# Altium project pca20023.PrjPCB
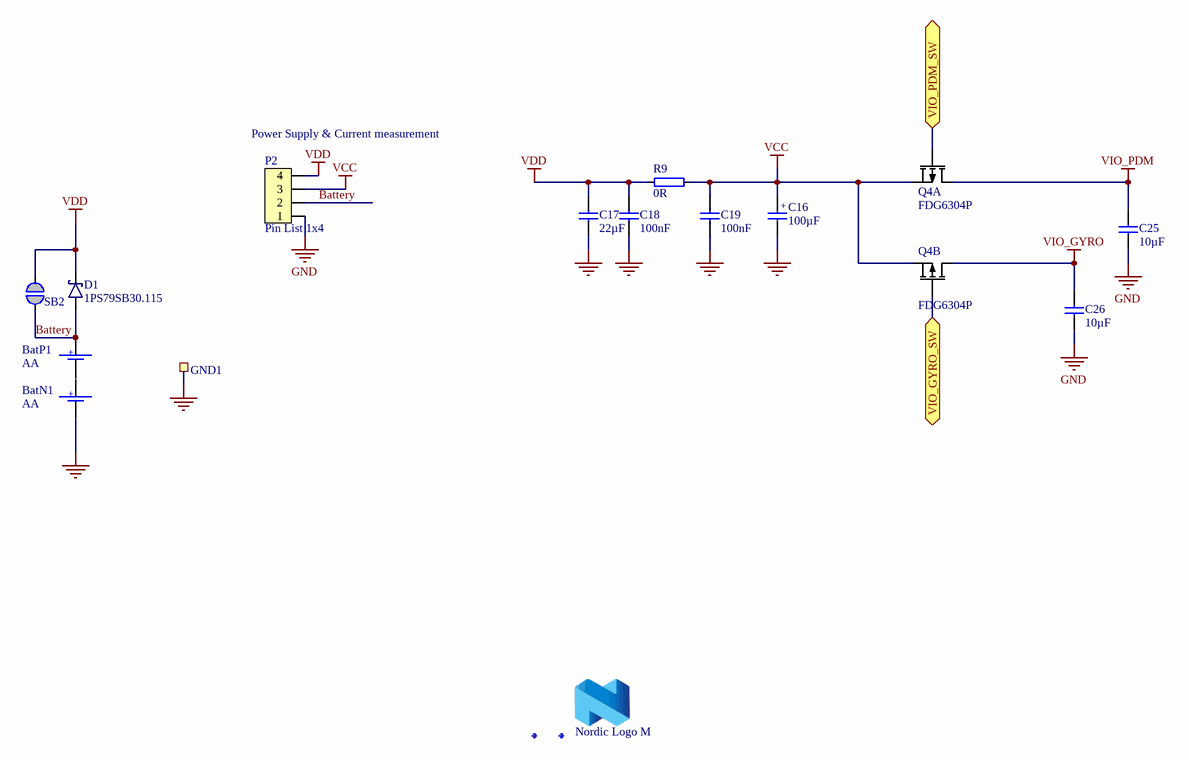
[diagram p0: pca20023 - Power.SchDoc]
5 sheets, 173 parts. Net scope: flat (ports and power ports of the same name join across sheets).
Board file: 400198.PcbDoc
Sheets:
  pca20023 - Power.SchDoc
  pca20023 - Keyboard.SchDoc
  pca20023 - Sensors.SchDoc
  pca20023 - IR&Mic&Buzzer.SchDoc
  pca20023 - Radio.SchDoc

## Sheet pca20023 - Power.SchDoc: Smart Remote 3 nRF52 Product Example - Power
size A4; DocumentNumber: 3; Revision: 1.0.0; SheetNumber: 2; SheetTotal: 5; DrawnBy: TORS; ProjectNumber: 4414; DocumentSize: A4; PCBRevision: 0044TORS; PCAName: PCA20023; PCBNumber: 400198

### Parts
BatN1  AA  [POLSATBATTERYHOLDER]
BatP1  AA  [POLSATBATTERYHOLDER]
C16  100µF  [CAPMP3528X21N]
C17  22µF  [CAPC2012X11L]
C18  100nF  [CAPC1005X04L]
C19  100nF  [CAPC1005X04L]
C25  10µF  [CAPC1608X06L]
C26  10µF  [CAPC1608X06L]
D1  1PS79SB30.115  [SOD-523]
Fid1  Fiducial mark  [Fiducial]  (value not drawn)
Fid2  Fiducial mark  [Fiducial]  (value not drawn)
GND1  2.0mm,SMD  [TP_SMD_2.0mmX2.0mm]  (value not drawn)  (no BOM)
LOGO1  Nordic Logo M  [NORDIC_LOGO_M]  (no BOM)
P2  Pin List 1x4  [LIST_1x4_SMD]
Q4  FDG6304P  [SOT65P210X100-6N]  (parts A,B of 2)
R9  0R  [RESC1005X04L]
SB2  Solderbridge  [Solderbridge]  (value not drawn)  (no BOM)

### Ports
VIO_GYRO_SW (bidir), VIO_PDM_SW (bidir)

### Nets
GND: BatN1.1 C16.2 C17.1 C18.1 C19.1 C25.1 C26.1 GND1.1 P2.1
VCC: C16.1 C19.2 P2.3 Q4.1(S1) Q4.4(S2) R9.2
VDD: C17.2 C18.2 D1.3(C) P2.4 R9.1 SB2.1
VIO_GYRO: C26.2 Q4.3(D2)
VIO_PDM: C25.2 Q4.6(D1)
Battery: BatP1.1 D1.1(A) P2.2 SB2.2
P0.07: Q4.5(G2) ; port VIO_GYRO_SW
P0.26: Q4.2(G1) ; port VIO_PDM_SW

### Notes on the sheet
- (near P2) Power Supply & Current measurement

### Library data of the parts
BatN1 = POLSATBATTERYHOLDER_N: Polsat Battery holder, Negative pole; Manufacturer Part Number: NA; Artikkelnr Noca: N.A.
BatP1 = POLSATBATTERYHOLDER_P: Polsat Battery holder, Positive pole; Manufacturer Part Number: NA; Artikkelnr Noca: N.A.
C16 = C3528-100µF: Capacitor, Tantalum, ±10%; Manufacturer: Vishay Sprague; Manufacturer Part Number: TR3B107K6R3C0500; Note: 6.3V; Artikkelnr Noca: N.A.
C17 = C0805-22µ: Capacitor, X5R, ±10%; Note: 6.3V; Artikkelnr Noca: 20039330; Artikkelnr Simpro: N.A.
C18 C19 = C0402-100n: Capacitor, X7R, ±10%; Note: 16V; Artikkelnr Noca: 20039200; Artikkelnr Simpro: N.A.
C25 C26 = C0603-10µ: Capacitor, X5R, ±20%; Note: 6.3V; Artikkelnr Noca: 20039234; Artikkelnr Simpro: N.A.
D1 = 1PS79SB30.115: Diode Schottky Vf=0.38, Vr=40V, If=200mA, Ir=500nA; Manufacturer: NXP; 2nd source part number: 873-4097; Artikkelnr Noca: 10029120; Artikkelnr Simpro: N.A.
Fid1 Fid2 = Fid-Mark: Artikkelnr Noca: N.A.
GND1 = TP_SMD_2.0MM: 2.0x2.0mm SMD testpad; Manufacturer: Nordic Semiconductor; Artikkelnr Noca: N.A.
LOGO1 = Nordic Logo M: Nordic Logo, medium size; Artikkelnr Noca: N.A.
P2 = Pin List 1x4 SMD: Pin List 1x4, 2.54mm (100mil), SMD; 2nd source part number: 179-8983; Artikkelnr Noca: 55019234; Artikkelnr Simpro: N.A.
Q4 = FDG6304P: Fairchild, FDG6304P, Dual P-Channel Digital FET; Manufacturer Part Number: FDG6304N; 2nd source part number: FDG6304PCT-ND; Artikkelnr Noca: 35029088; Artikkelnr Simpro: N.A.
R9 = R0402-0R: Resistor, ±5%, 0.063W; Note: Chip Res 5%; Artikkelnr Noca: 27049000; Artikkelnr Simpro: N.A.; Value Ohm: 0
SB2 = Solderbridge: Artikkelnr Noca: N.A.

## Sheet pca20023 - Keyboard.SchDoc: Smart Remote 3 nRF52 Product Example - Keyboard
size A4; DocumentNumber: 4; Revision: 1.0.0; SheetNumber: 3; SheetTotal: 5; DrawnBy: TORS; ProjectNumber: 4414; DocumentSize: A4; PCBRevision: 0044TORS; PCAName: PCA20023; PCBNumber: 400198
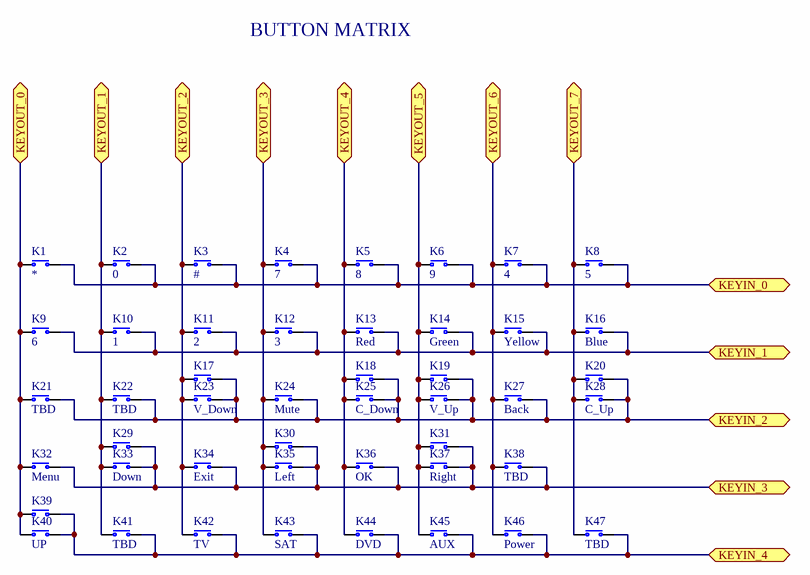
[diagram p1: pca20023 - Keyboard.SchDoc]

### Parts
K1  *  [PCB Switch]  (no BOM)
K2  0  [PCB Switch]  (no BOM)
K3  #  [PCB Switch]  (no BOM)
K4  7  [PCB Switch]  (no BOM)
K5  8  [PCB Switch]  (no BOM)
K6  9  [PCB Switch]  (no BOM)
K7  4  [PCB Switch]  (no BOM)
K8  5  [PCB Switch]  (no BOM)
K9  6  [PCB Switch]  (no BOM)
K10  1  [PCB Switch]  (no BOM)
K11  2  [PCB Switch]  (no BOM)
K12  3  [PCB Switch]  (no BOM)
K13  Red  [PCB Switch]  (no BOM)
K14  Green  [PCB Switch]  (no BOM)
K15  Yellow  [PCB Switch]  (no BOM)
K16  Blue  [PCB Switch]  (no BOM)
K17  PCB SW  [PCB Switch]  (value not drawn)  (no BOM)
K18  PCB SW  [PCB Switch]  (value not drawn)  (no BOM)
K19  PCB SW  [PCB Switch]  (value not drawn)  (no BOM)
K20  PCB SW  [PCB Switch]  (value not drawn)  (no BOM)
K21  TBD  [PCB Switch]  (no BOM)
K22  TBD  [PCB Switch]  (no BOM)
K23  V_Down  [PCB Switch]  (no BOM)
K24  Mute  [PCB Switch]  (no BOM)
K25  C_Down  [PCB Switch]  (no BOM)
K26  V_Up  [PCB Switch]  (no BOM)
K27  Back  [PCB Switch]  (no BOM)
K28  C_Up  [PCB Switch]  (no BOM)
K29  PCB SW  [PCB Switch]  (value not drawn)  (no BOM)
K30  PCB SW  [PCB Switch]  (value not drawn)  (no BOM)
K31  PCB SW  [PCB Switch]  (value not drawn)  (no BOM)
K32  Menu  [PCB Switch]  (no BOM)
K33  Down  [PCB Switch]  (no BOM)
K34  Exit  [PCB Switch]  (no BOM)
K35  Left  [PCB Switch]  (no BOM)
K36  OK  [PCB Switch]  (no BOM)
K37  Right  [PCB Switch]  (no BOM)
K38  TBD  [PCB Switch]  (no BOM)
K39  PCB SW  [PCB Switch]  (value not drawn)  (no BOM)
K40  UP  [PCB Switch]  (no BOM)
K41  TBD  [PCB Switch]  (no BOM)
K42  TV  [PCB Switch]  (no BOM)
K43  SAT  [PCB Switch]  (no BOM)
K44  DVD  [PCB Switch]  (no BOM)
K45  AUX  [PCB Switch]  (no BOM)
K46  Power  [PCB Switch]  (no BOM)
K47  TBD  [PCB Switch]  (no BOM)

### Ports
KEYIN_0 (bidir), KEYIN_1 (bidir), KEYIN_2 (bidir), KEYIN_3 (bidir), KEYIN_4 (bidir), KEYOUT_0 (bidir), KEYOUT_1 (bidir), KEYOUT_2 (bidir), KEYOUT_3 (bidir), KEYOUT_4 (bidir), KEYOUT_5 (bidir), KEYOUT_6 (bidir), KEYOUT_7 (bidir)

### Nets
P0.03: K5.2(COM) K13.2(COM) K18.2(COM) K25.2(COM) K36.2(COM) K44.2(COM) ; port KEYOUT_4
P0.08: K3.2(COM) K11.2(COM) K17.2(COM) K23.2(COM) K34.2(COM) K42.2(COM) ; port KEYOUT_2
P0.11: K4.2(COM) K12.2(COM) K24.2(COM) K30.2(COM) K35.2(COM) K43.2(COM) ; port KEYOUT_3
P0.12: K1.2(COM) K9.2(COM) K21.2(COM) K32.2(COM) K39.2(COM) K40.2(COM) ; port KEYOUT_0
P0.16: K1.1(N.O) K2.1(N.O) K3.1(N.O) K4.1(N.O) K5.1(N.O) K6.1(N.O) K7.1(N.O) K8.1(N.O) ; port KEYIN_0
P0.17: K9.1(N.O) K10.1(N.O) K11.1(N.O) K12.1(N.O) K13.1(N.O) K14.1(N.O) K15.1(N.O) K16.1(N.O) ; port KEYIN_1
P0.18: K17.1(N.O) K18.1(N.O) K19.1(N.O) K20.1(N.O) K21.1(N.O) K22.1(N.O) K23.1(N.O) K24.1(N.O) K25.1(N.O) K26.1(N.O) K27.1(N.O) K28.1(N.O) ; port KEYIN_2
P0.19: K39.1(N.O) K40.1(N.O) K41.1(N.O) K42.1(N.O) K43.1(N.O) K44.1(N.O) K45.1(N.O) K46.1(N.O) K47.1(N.O) ; port KEYIN_4
P0.20: K7.2(COM) K15.2(COM) K27.2(COM) K38.2(COM) K46.2(COM) ; port KEYOUT_6
P0.25: K8.2(COM) K16.2(COM) K20.2(COM) K28.2(COM) K47.2(COM) ; port KEYOUT_7
P0.27: K6.2(COM) K14.2(COM) K19.2(COM) K26.2(COM) K31.2(COM) K37.2(COM) K45.2(COM) ; port KEYOUT_5
P0.28: K2.2(COM) K10.2(COM) K22.2(COM) K29.2(COM) K33.2(COM) K41.2(COM) ; port KEYOUT_1
P0.29: K29.1(N.O) K30.1(N.O) K31.1(N.O) K32.1(N.O) K33.1(N.O) K34.1(N.O) K35.1(N.O) K36.1(N.O) K37.1(N.O) K38.1(N.O) ; port KEYIN_3

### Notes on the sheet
- BUTTON MATRIX

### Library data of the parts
K1-K16 K21-K28 K32-K38 K40-K47 = KEY_SWITCH_SR3: Keyboard matrix switch; Value: PCB SW; Artikkelnr Noca: N.A.
K17-K20 K29-K31 K39 = KEY_SWITCH_SR3: Keyboard matrix switch; Artikkelnr Noca: N.A.

## Sheet pca20023 - Sensors.SchDoc: Smart Remote 3 nRF52 Product Example - Sensors
size A4; DocumentNumber: 5; Revision: 1.0.0; SheetNumber: 4; SheetTotal: 5; DrawnBy: TORS; ProjectNumber: 4414; DocumentSize: A4; PCBRevision: 0044TORS; PCAName: PCA20023; PCBNumber: 400198
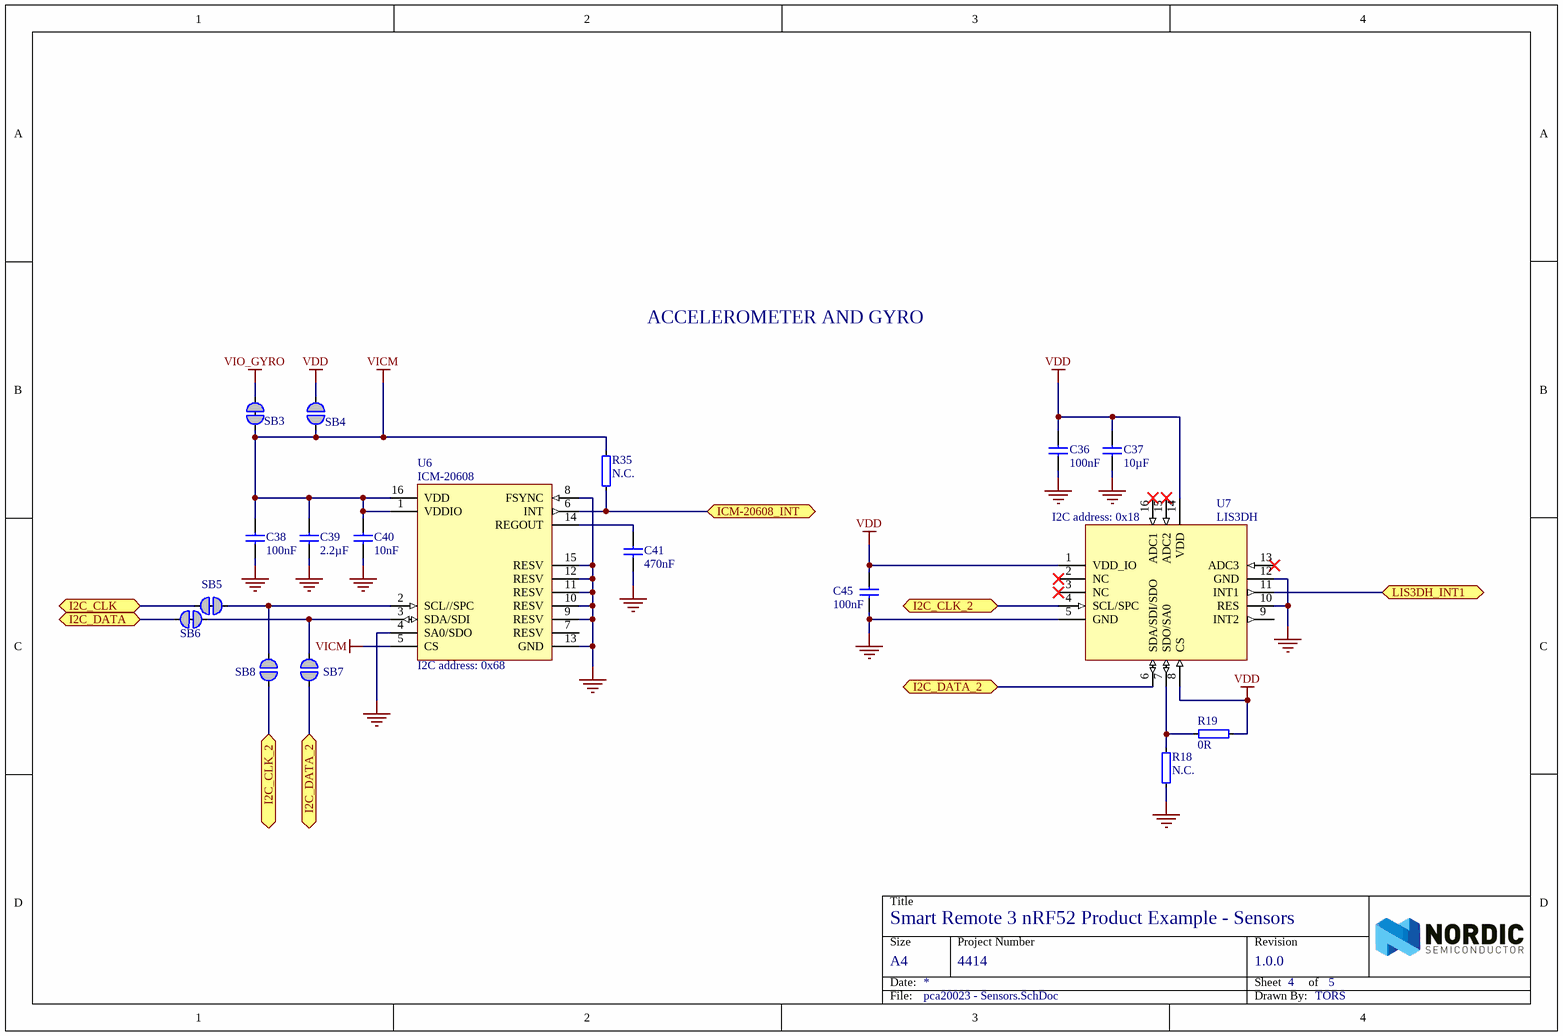
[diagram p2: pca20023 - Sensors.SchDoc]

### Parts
C36  100nF  [CAPC1005X04L]
C37  10µF  [CAPC2012X11L]
C38  100nF  [CAPC1005X04L]
C39  2.2µF  [CAPC1005X04L]
C40  10nF  [CAPC1005X04L]
C41  470nF  [CAPC1005X04L]
C45  100nF  [CAPC1005X04L]
R18  N.C.  [RESC1005X04L]
R19  0R  [RESC1005X04L]
R35  N.C.  [RESC1005X04L]
SB3  Solderbridge  [Solderbridge_Shorted]  (value not drawn)  (net tie, no BOM)
SB4  Solderbridge  [Solderbridge]  (value not drawn)  (no BOM)
SB5  Solderbridge  [Solderbridge_Shorted]  (value not drawn)  (net tie, no BOM)
SB6  Solderbridge  [Solderbridge_Shorted]  (value not drawn)  (net tie, no BOM)
SB7  Solderbridge  [Solderbridge]  (value not drawn)  (no BOM)
SB8  Solderbridge  [Solderbridge]  (value not drawn)  (no BOM)
U6  ICM-20608  [PQFN50P300X300X100-16N]
U7  LIS3DH  [PQFN50P300X300X100-16N]

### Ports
I2C_CLK (bidir), I2C_CLK_2 (bidir), I2C_DATA (bidir), I2C_DATA_2 (bidir), ICM-20608_INT (bidir), LIS3DH_INT1 (bidir)

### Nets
GND: C36.1 C37.1 C38.1 C39.1 C40.1 C41.1 C45.1 R18.1 U6.4(SA0/SDO) U6.8(FSYNC) U6.9(RESV) U6.10(RESV) U6.11(RESV) U6.12(RESV) U6.13(GND) U6.15(RESV) U7.5(GND) U7.10(RES) U7.12(GND)
VDD: C36.2 C37.2 C45.2 R19.2 SB4.1 U7.1(VDD_IO) U7.8(CS) U7.14(VDD)
VICM: C38.2 C39.2 C40.2 R35.2 SB3.2 SB4.2 U6.1(VDDIO) U6.5(CS) U6.16(VDD)
VIO_GYRO: SB3.1
P0.13: SB7.2 U7.6(SDA/SDI/SDO) ; port I2C_DATA_2
P0.14: SB8.2 U7.4(SCL/SPC) ; port I2C_CLK_2
P0.15: SB5.1 ; port I2C_CLK
P0.22: R35.1 U6.6(INT) ; port ICM-20608_INT
P0.30: U7.11(INT1) ; port LIS3DH_INT1
P0.31: SB6.1 ; port I2C_DATA
NetC41_2: C41.2 U6.14(REGOUT)
NetR18_2: R18.2 R19.1 U7.7(SDO/SA0)
NetSB5_2: SB5.2 SB8.1 U6.2(SCL//SPC)
NetSB6_2: SB6.2 SB7.1 U6.3(SDA/SDI)

Not connected (* = marked no-connect by the designer): U6 7(RESV); U7 2(NC)* 3(NC)* 9(INT2) 13(ADC3)* 15(ADC2)* 16(ADC1)*

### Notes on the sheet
- ACCELEROMETER AND GYRO
- (near U7) I2C address: 0x18
- (near U6) I2C address: 0x68

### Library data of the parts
C36 C38 C45 = C0402-100n: as C18 on sheet pca20023 - Power
C37 = C0805-10µ: Capacitor, X5R, ±10%; Note: 16V; Artikkelnr Noca: 20039243; Artikkelnr Simpro: N.A.
C39 = C0402-2µ2: Capacitor, X5R, ±20%; Note: 25V; Artikkelnr Noca: 20030006; Artikkelnr Simpro: N.A.
C40 = C0402-10n: Capacitor, X7R, ±10%; Note: 16V; Artikkelnr Noca: 20039166; Artikkelnr Simpro: N.A.
C41 = C0402-470n: Capacitor, X5R, ±10%; Note: 6.3V; Artikkelnr Noca: 20039350; Artikkelnr Simpro: N.A.
R18 R35 = R0402-N.C.: Not mounted; Note: Chip Res; Artikkelnr Noca: N.A.; Assembly: Not mounted
R19 = R0402-0R: as R9 on sheet pca20023 - Power
SB3 SB5 SB6 = Solderbridge Shorted: Shorted Solderbridge; Artikkelnr Noca: N.A.
SB4 SB7 SB8 = Solderbridge: Artikkelnr Noca: N.A.
U6 = ICM-20608: Gyroscope and Accelerometer, PQFN-16; Manufacturer: InvenSense; Artikkelnr Noca: N.A.
U7 = LIS3DH: 3-axis - ±2g/±4g/±8g/±16g digital output nano accelerometer; Manufacturer: STMicroelectronics; 2nd source part number: 187-2923; Note: MEMS digital output motion sensor ultra low-power high performance 3-axes "nano" accelerometer; Artikkelnr Noca: 15079978; Artikkelnr Simpro: N.A.

## Sheet pca20023 - IR&Mic&Buzzer.SchDoc: Smart Remote 3 nRF52 Product Example - IR&Mic&Buzzer
size A4; DocumentNumber: 5; Revision: 1.0.0; SheetNumber: 5; SheetTotal: 5; DrawnBy: TORS; ProjectNumber: 4414; DocumentSize: A4; PCBRevision: 0044TORS; PCAName: PCA20023; PCBNumber: 400198
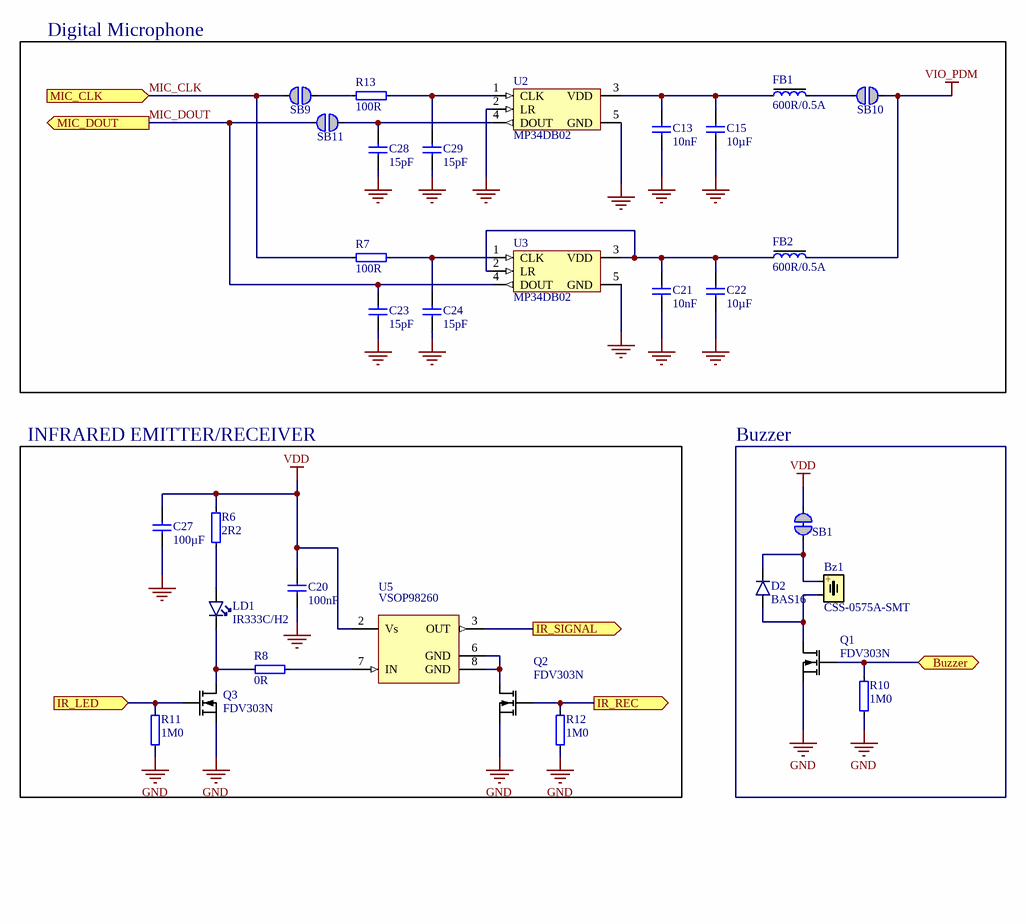
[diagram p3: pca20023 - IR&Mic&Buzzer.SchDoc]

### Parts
Bz1  CSS-0575A-SMT  [Buzzer_SMD_5x5_3-pin]
C13  10nF  [CAPC1005X04L]
C15  10µF  [CAPC2012X11L]
C20  100nF  [CAPC1005X04L]
C21  10nF  [CAPC1005X04L]
C22  10µF  [CAPC2012X11L]
C23  15pF  [CAPC1005X04L]
C24  15pF  [CAPC1005X04L]
C27  100µF  [CAPC3216X13L]
C28  15pF  [CAPC1005X04L]
C29  15pF  [CAPC1005X04L]
D2  BAS16  [SOT-23a]
FB1  600R/0.5A  [INDC1608X06L]
FB2  600R/0.5A  [INDC1608X06L]
LD1  IR333C/H2  [LED_3MM_SIDE]
Q1  FDV303N  [SOT-23a]
Q2  FDV303N  [SOT-23a]
Q3  FDV303N  [SOT-23a]
R6  2R2  [RESC1005X04L]
R7  100R  [RESC1005X04L]
R8  0R  [RESC1005X04L]
R10  1M0  [RESC1005X04L]
R11  1M0  [RESC1005X04L]
R12  1M0  [RESC1005X04L]
R13  100R  [RESC1005X04L]
SB1  Solderbridge  [Solderbridge_Shorted]  (value not drawn)  (net tie, no BOM)
SB9  Solderbridge  [Solderbridge]  (value not drawn)  (no BOM)
SB10  Solderbridge  [Solderbridge]  (value not drawn)  (no BOM)
SB11  Solderbridge  [Solderbridge]  (value not drawn)  (no BOM)
U2  MP34DB02  [RHLGA-4 (3x4x1mm)]
U3  MP34DB02  [RHLGA-4 (3x4x1mm)]
U5  VSOP98260  [QFN50P200X200X80-8N]

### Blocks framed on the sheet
Digital Microphone: C13 C15 C21-C24 C28 C29 FB1 FB2 R7 R13 SB9-SB11 U2 U3
INFRARED EMITTER/RECEIVER: C20 C27 LD1 Q2 Q3 R6 R8 R11 R12 U5

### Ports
Buzzer (bidir), IR_LED (in), IR_REC (out), IR_SIGNAL (out), MIC_CLK (in), MIC_DOUT (out)

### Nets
GND: C13.1 C15.1 C20.1 C21.1 C22.1 C23.1 C24.1 C27.1 C28.1 C29.1 Q1.2(S) Q2.2(S) Q3.2(S) R10.2 R11.1 R12.1 U2.2(LR) U2.5(GND) U3.5(GND)
VDD: C20.2 C27.2 R6.2 SB1.2 U5.2(Vs)
VIO_PDM: FB2.2 SB10.1
MIC_CLK: R7.1 SB9.2 ; port MIC_CLK
MIC_DOUT: C23.2 SB11.2 U3.4(DOUT) ; port MIC_DOUT
P0.04: Q1.1(G) R10.1 ; port Buzzer
P0.21: U5.3(OUT) ; port IR_SIGNAL
P0.23: Q2.1(G) R12.2 ; port IR_REC
P0.24: Q3.1(G) R11.2 ; port IR_LED
NetBz1_1: Bz1.1 D2.3(C) SB1.1
NetBz1_2: Bz1.2 D2.1(A) Q1.3(D)
NetC13_2: C13.2 C15.2 FB1.1 U2.3(VDD)
NetC21_2: C21.2 C22.2 FB2.1 U3.2(LR) U3.3(VDD)
NetC24_2: C24.2 R7.2 U3.1(CLK)
NetC28_2: C28.2 SB11.1 U2.4(DOUT)
NetC29_2: C29.2 R13.2 U2.1(CLK)
NetFB1_2: FB1.2 SB10.2
NetLD1_1: LD1.1(C) Q3.3(D) R8.1
NetLD1_2: LD1.2(A) R6.1
NetQ2_3: Q2.3(D) U5.6(GND) U5.8(GND)
NetR8_2: R8.2 U5.7(IN)
NetR13_1: R13.1 SB9.1

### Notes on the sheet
- Buzzer

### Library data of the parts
Bz1 = CSS-0575A-SMT: Magnetic Buzzer, SMD, 5.0mm x 5.0mm x 1.9mm, 4.0kHz, 75dB @ 3V, 2-4Vp-p, 110mA; Manufacturer: CUI Inc.; 2nd source part number: 490-CSS-0575A-SMT-TR; Artikkelnr Noca: N.A.
C13 C21 = C0402-10n: as C40 on sheet pca20023 - Sensors
C15 C22 = C0805-10µ: as C37 on sheet pca20023 - Sensors
C20 = C0402-100n: as C18 on sheet pca20023 - Power
C23 C24 C28 C29 = C0402-15p: Capacitor, NP0, ±5%; Note: 50V; Artikkelnr Noca: 20029141; Artikkelnr Simpro: N.A.
C27 = C1206-100u-6.3V: CAP CER 100UF 6.3V 20% X5R 1206; Manufacturer: Murata Electronics North America; Manufacturer Part Number: GRM31CR60J107ME39L; Artikkelnr Noca: N.A.
D2 = BAS16: Bas16 Diode; Artikkelnr Noca: 10019007; Artikkelnr Simpro: N.A.
FB1 FB2 = FB0603-600R@100MHz-500mA: Ferrite Bead, 600 Ohm @ 100MHz, 500mA, 380 mOhm Max; Manufacturer: Murata; Manufacturer Part Number: BLM18AG601SN1; 2nd source part number: 490-1014-1-ND; Note: Chip EMIFIL Inductor Type Chip Ferrite Bead; Artikkelnr Noca: 37019100; Artikkelnr Simpro: N.A.
LD1 = IR333C/H2_SIDE: IR EMITTER, 3MM, 940NM; Manufacturer: Everlight; Artikkelnr Noca: N.A.
Q1-Q3 = FDV303N: Mosfet FDV303N; 2nd source part number: FDV303NCT-ND; Note: Schottky; Artikkelnr Noca: 35029048; Artikkelnr Simpro: N.A.
R6 = R0402-2R2: Resistor, ±1%, 0.063W; Note: Chip Res 1%; Artikkelnr Noca: 27049009; Artikkelnr Simpro: N.A.; Value Ohm: 2.2
R7 R13 = R0402-100: Resistor, ±1%, 0.063W; Note: Chip Res 1%; Artikkelnr Noca: 27049049; Artikkelnr Simpro: N.A.; Value Ohm: 100
R8 = R0402-0R: as R9 on sheet pca20023 - Power
R10-R12 = R0402-1M0: Resistor, ±1%, 0.063W; Note: Chip Res 1%; Artikkelnr Noca: 27049145; Artikkelnr Simpro: N.A.; Value Ohm: 1000000
SB1 = Solderbridge Shorted: as SB3 on sheet pca20023 - Sensors
SB9-SB11 = Solderbridge: Artikkelnr Noca: N.A.
U2 U3 = MP34DB02: MEMS audio sensor omnidirectional digital microphone; Manufacturer: STMicroelectronics; 2nd source part number: 511-MP34DB02TR; Note: Alternative: ADMP421, SPK0833LM4H-B, MP34DB01; Artikkelnr Noca: N.A.
U5 = VSOP98260: IC SIGNAL CONDITIONING QFN; Manufacturer: Vishay; Artikkelnr Noca: N.A.

## Sheet pca20023 - Radio.SchDoc: Smart Remote 3 nRF52 Product Example - Radio
size A4; Organization: Nordic Semiconductor; DocumentNumber: 1; Revision: 1.0.0; SheetNumber: 1; SheetTotal: 5; CompanyName: Nordic Semiconductor; DrawnBy: TORS; ProjectNumber: 4414; DocumentSize: A4; PCAName: PCA20023; PCBRevision: 0044TORS; PCBNumber: 400198
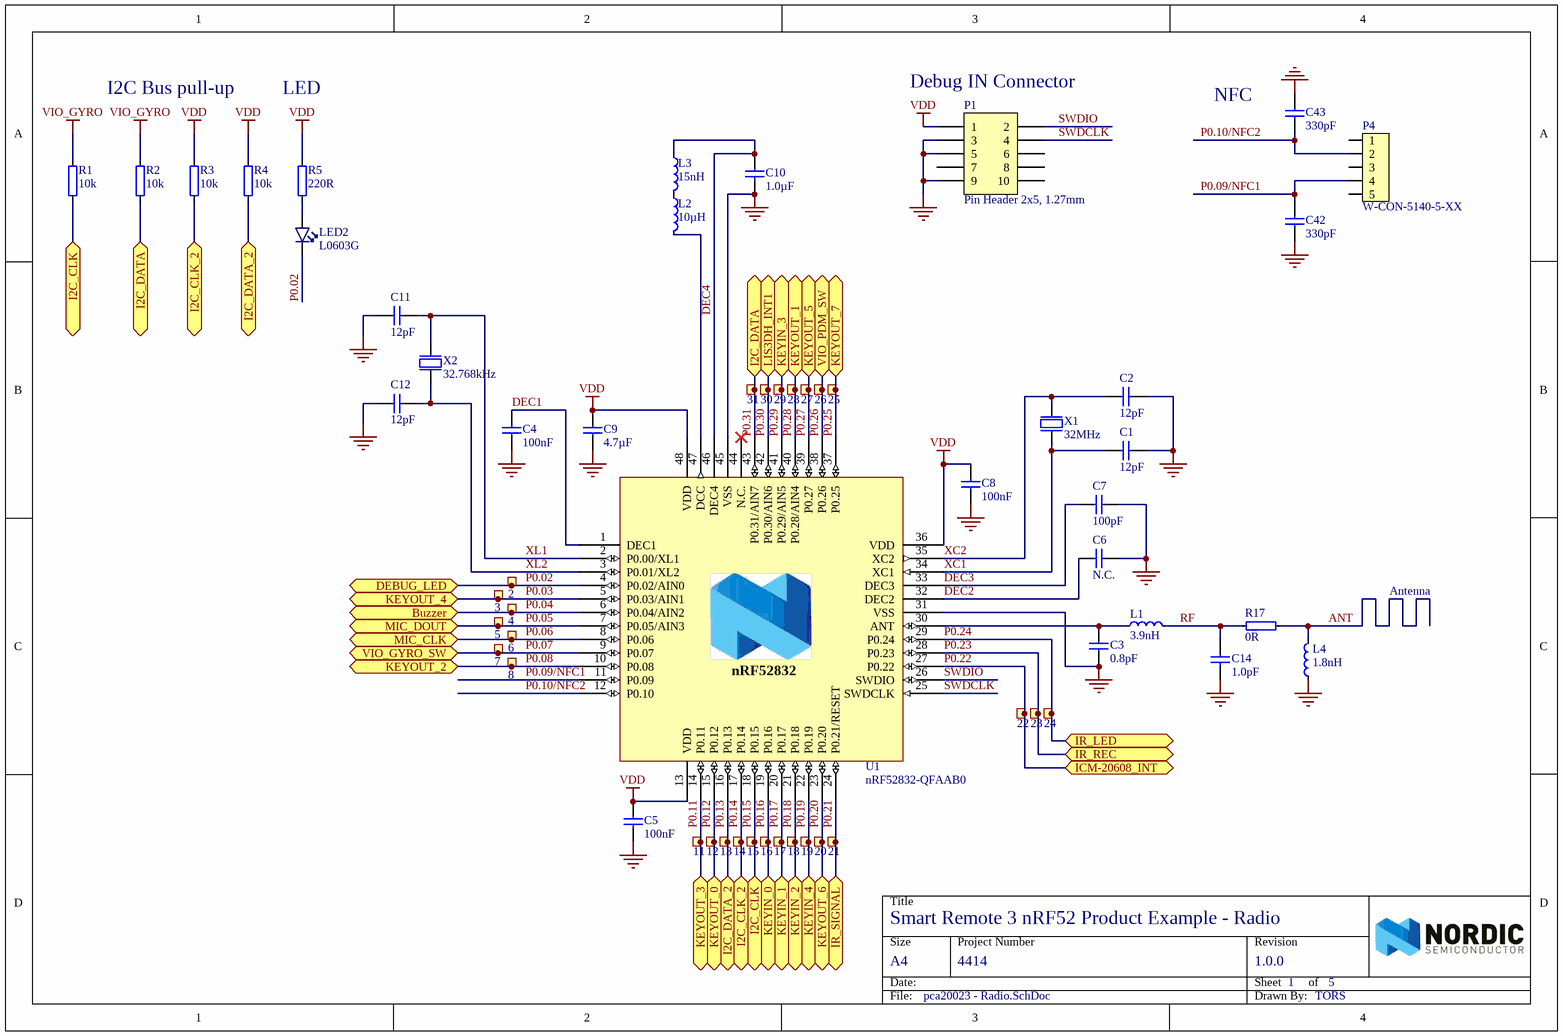
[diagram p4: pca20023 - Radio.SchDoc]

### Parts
2  Ø1.0mm,SMD  [TP_SMD_Ø1.0mm]  (value not drawn)  (no BOM)
3  Ø1.0mm,SMD  [TP_SMD_Ø1.0mm]  (value not drawn)  (no BOM)
4  Ø1.0mm,SMD  [TP_SMD_Ø1.0mm]  (value not drawn)  (no BOM)
5  Ø1.0mm,SMD  [TP_SMD_Ø1.0mm]  (value not drawn)  (no BOM)
6  Ø1.0mm,SMD  [TP_SMD_Ø1.0mm]  (value not drawn)  (no BOM)
7  Ø1.0mm,SMD  [TP_SMD_Ø1.0mm]  (value not drawn)  (no BOM)
8  Ø1.0mm,SMD  [TP_SMD_Ø1.0mm]  (value not drawn)  (no BOM)
11  Ø1.0mm,SMD  [TP_SMD_Ø1.0mm]  (value not drawn)  (no BOM)
12  Ø1.0mm,SMD  [TP_SMD_Ø1.0mm]  (value not drawn)  (no BOM)
13  Ø1.0mm,SMD  [TP_SMD_Ø1.0mm]  (value not drawn)  (no BOM)
14  Ø1.0mm,SMD  [TP_SMD_Ø1.0mm]  (value not drawn)  (no BOM)
15  Ø1.0mm,SMD  [TP_SMD_Ø1.0mm]  (value not drawn)  (no BOM)
16  Ø1.0mm,SMD  [TP_SMD_Ø1.0mm]  (value not drawn)  (no BOM)
17  Ø1.0mm,SMD  [TP_SMD_Ø1.0mm]  (value not drawn)  (no BOM)
18  Ø1.0mm,SMD  [TP_SMD_Ø1.0mm]  (value not drawn)  (no BOM)
19  Ø1.0mm,SMD  [TP_SMD_Ø1.0mm]  (value not drawn)  (no BOM)
20  Ø1.0mm,SMD  [TP_SMD_Ø1.0mm]  (value not drawn)  (no BOM)
21  Ø1.0mm,SMD  [TP_SMD_Ø1.0mm]  (value not drawn)  (no BOM)
22  Ø1.0mm,SMD  [TP_SMD_Ø1.0mm]  (value not drawn)  (no BOM)
23  Ø1.0mm,SMD  [TP_SMD_Ø1.0mm]  (value not drawn)  (no BOM)
24  Ø1.0mm,SMD  [TP_SMD_Ø1.0mm]  (value not drawn)  (no BOM)
25  Ø1.0mm,SMD  [TP_SMD_Ø1.0mm]  (value not drawn)  (no BOM)
26  Ø1.0mm,SMD  [TP_SMD_Ø1.0mm]  (value not drawn)  (no BOM)
27  Ø1.0mm,SMD  [TP_SMD_Ø1.0mm]  (value not drawn)  (no BOM)
28  Ø1.0mm,SMD  [TP_SMD_Ø1.0mm]  (value not drawn)  (no BOM)
29  Ø1.0mm,SMD  [TP_SMD_Ø1.0mm]  (value not drawn)  (no BOM)
30  Ø1.0mm,SMD  [TP_SMD_Ø1.0mm]  (value not drawn)  (no BOM)
31  Ø1.0mm,SMD  [TP_SMD_Ø1.0mm]  (value not drawn)  (no BOM)
C1  12pF  [CAPC1005X04L]
C2  12pF  [CAPC1005X04L]
C3  0.8pF  [CAPC1005X04L]
C4  100nF  [CAPC1005X04L]
C5  100nF  [CAPC1005X04L]
C6  N.C.  [CAPC1005X04L]
C7  100pF  [CAPC1005X04L]
C8  100nF  [CAPC1005X04L]
C9  4.7µF  [CAPC1608X06L]
C10  1.0µF  [CAPC1608X06L]
C11  12pF  [CAPC1005X04L]
C12  12pF  [CAPC1005X04L]
C14  1.0pF  [CAPC1005X04L]
C42  330pF  [CAPC1005X04L]
C43  330pF  [CAPC1005X04L]
L1  3.9nH  [INDC1005X04L]
L2  10µH  [INDC1608X06L]
L3  15nH  [INDC1005X04L]
L4  1.8nH  [INDC1005X04L]
LED2  L0603G  [LED_0603_G]
P1  Pin Header 2x5, 1.27mm  [HDR_2x5-SMD-1.27mm-K]
P4  W-CON-5140-5-XX  [W-CON-5140-5-XX]
R1  10k  [RESC1005X04L]
R2  10k  [RESC1005X04L]
R3  10k  [RESC1005X04L]
R4  10k  [RESC1005X04L]
R5  220R  [RESC1005X04L]
R17  0R  [RESC1005X04L]
U1  nRF52832-QFAAB0  [QFN40P600X600X90-48N]
X1  32MHz  [BT-XTAL_2016]
X2  32.768kHz  [XTAL_3215]

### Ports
Buzzer (bidir), DEBUG_LED (bidir), I2C_CLK (bidir), I2C_CLK_2 (bidir), I2C_DATA (bidir), I2C_DATA_2 (bidir), ICM-20608_INT (bidir), IR_LED (bidir), IR_REC (bidir), IR_SIGNAL (bidir), KEYIN_0 (bidir), KEYIN_1 (bidir), KEYIN_2 (bidir), KEYIN_3 (bidir), KEYIN_4 (bidir), KEYOUT_0 (bidir), KEYOUT_1 (bidir), KEYOUT_2 (bidir), KEYOUT_3 (bidir), KEYOUT_4 (bidir), KEYOUT_5 (bidir), KEYOUT_6 (bidir), KEYOUT_7 (bidir), LIS3DH_INT1 (bidir), MIC_CLK (bidir), MIC_DOUT (bidir), VIO_GYRO_SW (bidir), VIO_PDM_SW (bidir)

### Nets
GND: C1.2 C2.2 C3.1 C4.2 C5.2 C6.1 C7.2 C8.2 C9.2 C10.1 C11.2 C12.2 C14.2 C42.2 C43.1 L4.1 P1.3 P1.5 P1.9 U1.31(VSS) U1.45(VSS) U1.49(GND) X1.2(GND) X1.4(GND)
VDD: C5.1 C8.1 C9.1 P1.1 R3.2 R4.2 R5.2 U1.13(VDD) U1.36(VDD) U1.48(VDD)
VIO_GYRO: R1.2 R2.2
ANT: L4.2 R17.2
DEC1: C4.1 U1.1(DEC1)
DEC2: C6.2 U1.32(DEC2)
DEC3: C7.1 U1.33(DEC3)
DEC4: C10.2 L3.1 U1.46(DEC4)
P0.02: 2.1 LED2.1(C) U1.4(P0.02/AIN0) ; port DEBUG_LED
P0.03: 3.1 U1.5(P0.03/AIN1) ; port KEYOUT_4
P0.04: 4.1 U1.6(P0.04/AIN2) ; port Buzzer
P0.05: 5.1 U1.7(P0.05/AIN3) ; port MIC_DOUT  [project net MIC_DOUT]
P0.06: 6.1 U1.8(P0.06) ; port MIC_CLK  [project net MIC_CLK]
P0.07: 7.1 U1.9(P0.07) ; port VIO_GYRO_SW
P0.08: 8.1 U1.10(P0.08) ; port KEYOUT_2
P0.09/NFC1: C42.1 P4.4 U1.11(P0.09)
P0.10/NFC2: C43.2 P4.2 U1.12(P0.10)
P0.11: 11.1 U1.14(P0.11) ; port KEYOUT_3
P0.12: 12.1 U1.15(P0.12) ; port KEYOUT_0
P0.13: 13.1 R4.1 U1.16(P0.13) ; port I2C_DATA_2
P0.14: 14.1 R3.1 U1.17(P0.14) ; port I2C_CLK_2
P0.15: 15.1 R1.1 U1.18(P0.15) ; port I2C_CLK
P0.16: 16.1 U1.19(P0.16) ; port KEYIN_0
P0.17: 17.1 U1.20(P0.17) ; port KEYIN_1
P0.18: 18.1 U1.21(P0.18) ; port KEYIN_2
P0.19: 19.1 U1.22(P0.19) ; port KEYIN_4
P0.20: 20.1 U1.23(P0.20) ; port KEYOUT_6
P0.21: 21.1 U1.24(P0.21/RESET) ; port IR_SIGNAL
P0.22: 22.1 U1.27(P0.22) ; port ICM-20608_INT
P0.23: 23.1 U1.28(P0.23) ; port IR_REC
P0.24: 24.1 U1.29(P0.24) ; port IR_LED
P0.25: 25.1 U1.37(P0.25) ; port KEYOUT_7
P0.26: 26.1 U1.38(P0.26) ; port VIO_PDM_SW
P0.27: 27.1 U1.39(P0.27) ; port KEYOUT_5
P0.28: 28.1 U1.40(P0.28/AIN4) ; port KEYOUT_1
P0.29: 29.1 U1.41(P0.29/AIN5) ; port KEYIN_3
P0.30: 30.1 U1.42(P0.30/AIN6) ; port LIS3DH_INT1
P0.31: 31.1 R2.1 U1.43(P0.31/AIN7) ; port I2C_DATA
RF: C14.1 L1.2 R17.1
SWDCLK: P1.4 U1.25(SWDCLK)
SWDIO: P1.2 U1.26(SWDIO)
XC1: C1.1 U1.34(XC1) X1.1(inp)
XC2: C2.1 U1.35(XC2) X1.3(out)
XL1: C11.1 U1.2(P0.00/XL1) X2.1(inp)
XL2: C12.1 U1.3(P0.01/XL2) X2.2(out)
NetC3_2: C3.2 L1.1 U1.30(ANT)
NetL2_1: L2.1 L3.2
NetL2_2: L2.2 U1.47(DCC)
NetLED2_2: LED2.2(A) R5.1

Not connected (* = marked no-connect by the designer): P1 6 7 8 10; P4 1 3 5; U1 44(N.C.)*

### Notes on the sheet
- I2C Bus pull-up
- LED
- (near P1) Debug IN Connector
- (near C43) NFC
- Antenna

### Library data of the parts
2-8 11-31 = TP_SMD_Ø1.0MM: 1.0mm circular SMD testpad; Manufacturer: Nordic Semiconductor; Artikkelnr Noca: N.A.
C1 C2 C11 C12 = C0402-12p: Capacitor, NP0, ±2%; Note: 50V; Artikkelnr Noca: 20029159; Artikkelnr Simpro: N.A.
C3 = C0402-0.8p: Capacitor, NP0, ±5%; Note: 50V; Artikkelnr Noca: 20029147; Artikkelnr Simpro: N.A.
C4 C5 C8 = C0402-100n: as C18 on sheet pca20023 - Power
C6 = C0402-N.C.: Not mounted; Note: Chip Cap; Artikkelnr Noca: N.A.; Assembly: Not mounted
C7 = C0402-100p: Capacitor, NP0, ±5%; Note: 50V; Artikkelnr Noca: 20029135; Artikkelnr Simpro: N.A.
C9 = C0603-4µ7: Capacitor, X5R, ±10%; Note: 6.3V; Artikkelnr Noca: 20069060; Artikkelnr Simpro: N.A.
C10 = C0603-1µ0: Capacitor, X7R, ±10%; Note: 16V; Artikkelnr Noca: 20039335; Artikkelnr Simpro: N.A.
C14 = C0402-1.0p: Capacitor, NP0, ±0.1pF; Note: 50V; Artikkelnr Noca: 20029140; Artikkelnr Simpro: N.A.
C42 C43 = C0402-330p: Capacitor, NP0, ±5%; Note: Chip Cap 1%; Artikkelnr Noca: N.A.
L1 = L0402-3n9: Inductor, 170mA, ±0.1nH; Manufacturer: Murata; Manufacturer Part Number: LQP15MN3N9B02D; Note: High frequency chip inductor ±5%; Artikkelnr Noca: 33029151; Artikkelnr Simpro: N.A.
L2 = L0603-10µ: Inductor, 80mA, ±10%; Manufacturer: Taiyo Yuden; Manufacturer Part Number: LBMF1608T100K; 2nd source part number: 178-6105; Note: LBMF1608T100K 10µH 80mA 0603; Artikkelnr Noca: 33029314; Artikkelnr Simpro: N.A.
L3 = L0402-15n: Inductor, 320mA, ±5%; Manufacturer: Taiyo Yuden; Manufacturer Part Number: HK100515NJ-T; 2nd source part number: 658-1328; Note: High frequency chip inductor ±10%; Artikkelnr Noca: 33029323; Artikkelnr Simpro: N.A.
L4 = L0402-1n8: Inductor, 280mA, ±0.1nH; Manufacturer: Murata; Manufacturer Part Number: LQP15MN1N8B02D; Note: High frequency chip inductor ±5%; Artikkelnr Noca: 33029171; Artikkelnr Simpro: N.A.
LED2 = EL19-21SYGC: LED 0603, EL19-21SYGC; Manufacturer: Everlight; Manufacturer Part Number: 19-21SYGC/S530-E1/TR8; Note: 16 mcd @ 20 mA; Artikkelnr Noca: 13019044; Artikkelnr Simpro: N.A.
P1 = Pin Header 2x5 SMD, 1.27mm, KS: Pin Header 2x5, 1.27mm (50mil), SMD, Keying Shroud; Manufacturer: W-CON; Manufacturer Part Number: 3132-10MS0BK00R1; 2nd source part number: FTSH-105-01-F-DV-K; Artikkelnr Noca: 55010009; Artikkelnr Simpro: N.A.
P4 = W-CON-5140-5-XX: *; Manufacturer: W-CON; Manufacturer Part Number: 5140-05-SMUWBX02; Artikkelnr Noca: N.A.
R1-R4 = R0402-10k: Resistor, ±1%, 0.063W; Note: Chip Res 1%; Artikkelnr Noca: 27049097; Artikkelnr Simpro: N.A.; Value Ohm: 10000
R5 = R0402-220: Resistor, ±1%, 0.063W; Note: Chip Res 1%; Artikkelnr Noca: 27049057; Artikkelnr Simpro: N.A.; Value Ohm: 220
R17 = R0402-0R: as R9 on sheet pca20023 - Power
U1 = nRF52832-QFAAB0: Multi-protocol Bluetooth Low Energy, ANT and 2.4GHz proprietary system-on-chip; Manufacturer: Nordic Semiconductor; Artikkelnr Noca: 15079334; Artikkelnr Simpro: N.A.
X1 = XTAL_SMD2016_32MHz_8pF_Epson: XTAL SMD 2016, 32MHz, Cl=8pF, Tol: ±10ppm, Stab: ±10ppm; Manufacturer: Epson Toyocom; Manufacturer Part Number: Q22FA12800025; Note: XTAL SMD 32.000MHz; Artikkelnr Noca: 22019238; Artikkelnr Simpro: N.A.
X2 = XTAL_FC-135 32.768k: XTAL SMD 3215, 32.768kHz, 9pF, ±20ppm; Manufacturer: Epson Toyocom; Manufacturer Part Number: FC-135 32.768KHZ ±20PPM,9.0PF; 2nd source part number: 127-8037; Note: XTAL SMD 32.768kHz, 3215; Artikkelnr Noca: 22019091; Artikkelnr Simpro: N.A.

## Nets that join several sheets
GND: pca20023 - Power (9 pins), pca20023 - Sensors (19 pins), pca20023 - IR&Mic&Buzzer (19 pins), pca20023 - Radio (24 pins)
VDD: pca20023 - Power (6 pins), pca20023 - Sensors (8 pins), pca20023 - IR&Mic&Buzzer (5 pins), pca20023 - Radio (10 pins)
VIO_GYRO: pca20023 - Power (C26.2 Q4.3), pca20023 - Sensors (SB3.1), pca20023 - Radio (R1.2 R2.2)
VIO_PDM: pca20023 - Power (C25.2 Q4.6), pca20023 - IR&Mic&Buzzer (FB2.2 SB10.1)
MIC_CLK: pca20023 - IR&Mic&Buzzer (R7.1 SB9.2), pca20023 - Radio (6.1 U1.8)
MIC_DOUT: pca20023 - IR&Mic&Buzzer (C23.2 SB11.2 U3.4), pca20023 - Radio (5.1 U1.7)
P0.03: pca20023 - Keyboard (6 pins), pca20023 - Radio (3.1 U1.5)
P0.04: pca20023 - IR&Mic&Buzzer (Q1.1 R10.1), pca20023 - Radio (4.1 U1.6)
P0.07: pca20023 - Power (Q4.5), pca20023 - Radio (7.1 U1.9)
P0.08: pca20023 - Keyboard (6 pins), pca20023 - Radio (8.1 U1.10)
P0.11: pca20023 - Keyboard (6 pins), pca20023 - Radio (11.1 U1.14)
P0.12: pca20023 - Keyboard (6 pins), pca20023 - Radio (12.1 U1.15)
P0.13: pca20023 - Sensors (SB7.2 U7.6), pca20023 - Radio (13.1 R4.1 U1.16)
P0.14: pca20023 - Sensors (SB8.2 U7.4), pca20023 - Radio (14.1 R3.1 U1.17)
P0.15: pca20023 - Sensors (SB5.1), pca20023 - Radio (15.1 R1.1 U1.18)
P0.16: pca20023 - Keyboard (8 pins), pca20023 - Radio (16.1 U1.19)
P0.17: pca20023 - Keyboard (8 pins), pca20023 - Radio (17.1 U1.20)
P0.18: pca20023 - Keyboard (12 pins), pca20023 - Radio (18.1 U1.21)
P0.19: pca20023 - Keyboard (9 pins), pca20023 - Radio (19.1 U1.22)
P0.20: pca20023 - Keyboard (5 pins), pca20023 - Radio (20.1 U1.23)
P0.21: pca20023 - IR&Mic&Buzzer (U5.3), pca20023 - Radio (21.1 U1.24)
P0.22: pca20023 - Sensors (R35.1 U6.6), pca20023 - Radio (22.1 U1.27)
P0.23: pca20023 - IR&Mic&Buzzer (Q2.1 R12.2), pca20023 - Radio (23.1 U1.28)
P0.24: pca20023 - IR&Mic&Buzzer (Q3.1 R11.2), pca20023 - Radio (24.1 U1.29)
P0.25: pca20023 - Keyboard (5 pins), pca20023 - Radio (25.1 U1.37)
P0.26: pca20023 - Power (Q4.2), pca20023 - Radio (26.1 U1.38)
P0.27: pca20023 - Keyboard (7 pins), pca20023 - Radio (27.1 U1.39)
P0.28: pca20023 - Keyboard (6 pins), pca20023 - Radio (28.1 U1.40)
P0.29: pca20023 - Keyboard (10 pins), pca20023 - Radio (29.1 U1.41)
P0.30: pca20023 - Sensors (U7.11), pca20023 - Radio (30.1 U1.42)
P0.31: pca20023 - Sensors (SB6.1), pca20023 - Radio (31.1 R2.1 U1.43)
